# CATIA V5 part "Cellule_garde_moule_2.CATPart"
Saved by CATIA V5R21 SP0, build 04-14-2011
Part number: Moule_cellule_garde
Bounding box of the stored display mesh (mm): x -30 to 30, y -120 to 120, z -20 to 0
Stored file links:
  C:\Users\zerma\Pictures\CAO\Cellule_garde_moule_2.CATPart
  Product1.CATProduct
  C:\Users\zerma\Pictures\CAO\Moule_v1.CATPart
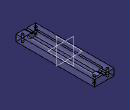
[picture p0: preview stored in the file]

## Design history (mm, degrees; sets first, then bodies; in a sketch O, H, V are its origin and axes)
Body1 (main body)
  Sketch1 on yz-plane, origin (0, 0, 0), H (0, 1, 0), V (0, 0, 1)
    line L1 (-95, -12.5) -> (95, -12.5)
    point P1 (-95, -12.5)
    line L2 (-100, -15) -> (100, -15)
    point P3 (-100, -15)
    line L3 (-95, -12.5) -> (-95, 0)
    point P5 (-95, 0)
    line L4 (-100, -15) -> (-100, 0)
    point P6 (-100, 0)
    line L5 (-95, 0) -> (-100, 0)
    point P7 (100, 0)
    point P8 (100, -15)
    line L6 (100, -15) -> (100, 0)
    point P9 (95, 0)
    line L7 (95, 0) -> (100, 0)
    point P10 (95, -12.5)
    line L8 (95, -12.5) -> (95, 0)
    distance L1 H = 12.5
    distance L1 L2 = 2.5
    length L4 = 15
    distance L4 L3 = 5
    length L1 = 190
    length L2 = 200
    distance V L3 = 95
    horizontal: L1 H, L2 H, L5 H
    vertical: L3 V, L4 V
    symmetry: P6 P7 V, P3 P8 V, L4 L6 V, P5 P9 V, L5 L7 V, P1 P10 V, L3 L8 V
  Shaft1: profile Sketch1, axis Sketch1.H, angle 360
  Sketch2 on face of Shaft1 from Sketch1.L4, origin (0, -100, 0), H (1, 0, 0), V (0, 0, 1)
    line L1 (-10, 2.5) -> (10, 2.5)
    line L2 (10, 2.5) -> (10, -2.5)
    line L3 (10, -2.5) -> (-10, -2.5)
    line L4 (-10, -2.5) -> (-10, 2.5)
    length L2 = 5
    length L1 = 20
    horizontal: L1 H, L3 H
    vertical: L2 V, L4 V
    symmetry: L3 L1 H, L4 L2 V
  Pad1: profile Sketch2, direction (0, -1, 0), length 15
  Sketch3 on face of Pad1 from Sketch2.L1, origin (0, 0, 2.5), H (1, 0, 0), V (0, 1, 0)
    circle A1 centre (0, -107.5) radius 2.5
    point P1 (0, -107.5)
    reference intersected line E1 (14.7902, -100) -> (-14.7902, -100) from face of Shaft1 from Sketch1.L4
    radius A1 = 2.5
    distance P1 E1 = 7.5
    coincidence: P1 V
  Pocket1: profile Sketch3, direction (0, 0, -1), length 5, mirrored extent
  Fillet1: radius 2, on edge [face of Pad1 from Sketch2.L4 | end face of Pad1]; edge [face of Pad1 from Sketch2.L1 | end face of Pad1]; edge [face of Pad1 from Sketch2.L3 | end face of Pad1]; edge [face of Pad1 from Sketch2.L2 | end face of Pad1]; edge [face of Pad1 from Sketch2.L2 | face of Pad1 from Sketch2.L3]; edge [face of Shaft1 from Sketch1.L4 | face of Pad1 from Sketch2.L3]; edge [face of Pad1 from Sketch2.L3 | face of Pad1 from Sketch2.L4]; edge [face of Pocket1 from Sketch3.A1 | face of Pad1 from Sketch2.L3]; edge [face of Pad1 from Sketch2.L4 | face of Pad1 from Sketch2.L1]; edge [face of Pad1 from Sketch2.L1 | face of Pad1 from Sketch2.L2]; edge [face of Shaft1 from Sketch1.L4 | face of Pad1 from Sketch2.L1]; edge [face of Shaft1 from Sketch1.L4 | face of Pad1 from Sketch2.L4]; edge [face of Shaft1 from Sketch1.L4 | face of Pad1 from Sketch2.L2]; face of Pad1 from Sketch2.L1
  Mirror1: of Pad1, Pocket1, Fillet1, about zx-plane
  Fillet2: radius 4, on edge [face of Shaft1 from Sketch1.L2 | face of Shaft1 from Sketch1.L6]; edge [face of Shaft1 from Sketch1.L4 | face of Shaft1 from Sketch1.L2]
Body2
  Sketch4 on xy-plane, origin (0, 0, 0), H (1, 0, 0), V (0, 1, 0)
    line L1 (30, 120) -> (30, -120)
    line L2 (30, -120) -> (-30, -120)
    line L3 (-30, -120) -> (-30, 120)
    line L4 (-30, 120) -> (30, 120)
    vertical: L1 V, L3 V
    horizontal: L2 H, L4 H
    equidistance: L1 L3 O, L2 L4 O
  Pad2: profile Sketch4, direction (0, 0, -1), length 20
  Body3
    Sketch5 on yz-plane, origin (0, 0, 0), H (0, 1, 0), V (0, 0, 1)
      line L1 (-95, -12.5) -> (95, -12.5)
      point P1 (-95, -12.5)
      line L2 (-100, -15) -> (100, -15)
      point P3 (-100, -15)
      line L3 (-95, -12.5) -> (-95, 0)
      point P5 (-95, 0)
      line L4 (-100, -15) -> (-100, -4)
      point P6 (-100, -4)
      point P7 (100, -4)
      point P8 (100, -15)
      line L5 (100, -15) -> (100, -4)
      point P9 (95, 0)
      point P10 (95, -12.5)
      line L6 (95, -12.5) -> (95, 0)
      line L7 (-100, -4) -> (-120, -4)
      line L8 (-120, -4) -> (-120, 0)
      line L9 (-120, 0) -> (-95, 0)
      point P13 (-95, 0)
      line L10 (100, -4) -> (120, -4)
      line L11 (120, -4) -> (120, 0)
      line L12 (120, 0) -> (95, 0)
      distance L1 H = 12.5
      distance L1 L2 = 2.5
      length L4 = 11
      distance L4 L3 = 5
      length L1 = 190
      length L2 = 200
      distance V L3 = 95
      length L9 = 25
      length L12 = 25
      length L11 = 4
      horizontal: L1 H, L2 H, L7 H, L9 H, L10 H, L12 H
      vertical: L3 V, L4 V, L8 V, L11 V
      symmetry: P6 P7 V, P3 P8 V, L4 L5 V, P5 P9 V, P1 P10 V, L3 L6 V
      coincidence: P13 P5
    Shaft2: profile Sketch5, axis Sketch5.H, angle 360
  Remove1: tool Body3
  Sketch6 on face of Shaft2 from Sketch5.L6, origin (0, 95, 0), H (-1, 0, 0), V (0, 0, 1)
    circle A1 centre (0, 0) radius 12.5
    reference projected circle E1 centre (0, 0) radius 12.5 from edge [face of Shaft2 from Sketch5.L1 | face of Shaft2 from Sketch5.L6]
    reference projected circle E2 centre (0, 0) radius 12.5 from edge [face of Shaft2 from Sketch5.L1 | face of Shaft2 from Sketch5.L6]
    coincidence: A1 E1
    concentricity: A1 E2
  Pocket2: profile Sketch6, direction (0, -1, 0), up to face of Shaft2 from Sketch5.L3
  Sketch7 on end face of Pad2, origin (0, 0, -20), H (1, 0, 0), V (0, -1, 0)
    circle A1 centre (20, 110) radius 3.5
    point P1 (20, 110)
    circle A2 centre (20, -110) radius 3.5
    circle A3 centre (-20, 110) radius 3.5
    circle A4 centre (-20, -110) radius 3.5
    reference projected line E1 (30, 120) -> (30, -120) from edge [end face of Pad2 | face of Pad2 from Sketch4.L1]
    reference projected line E2 (-30, 120) -> (30, 120) from edge [end face of Pad2 | face of Pad2 from Sketch4.L2]
    radius A1 = 3.5
    distance P1 E1 = 10
    distance P1 E2 = 10
    symmetry: A1 A2 H, A1 A3 V, A3 A4 H
  Pocket3: profile Sketch7, direction (0, 0, 1), length 50, mirrored extent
